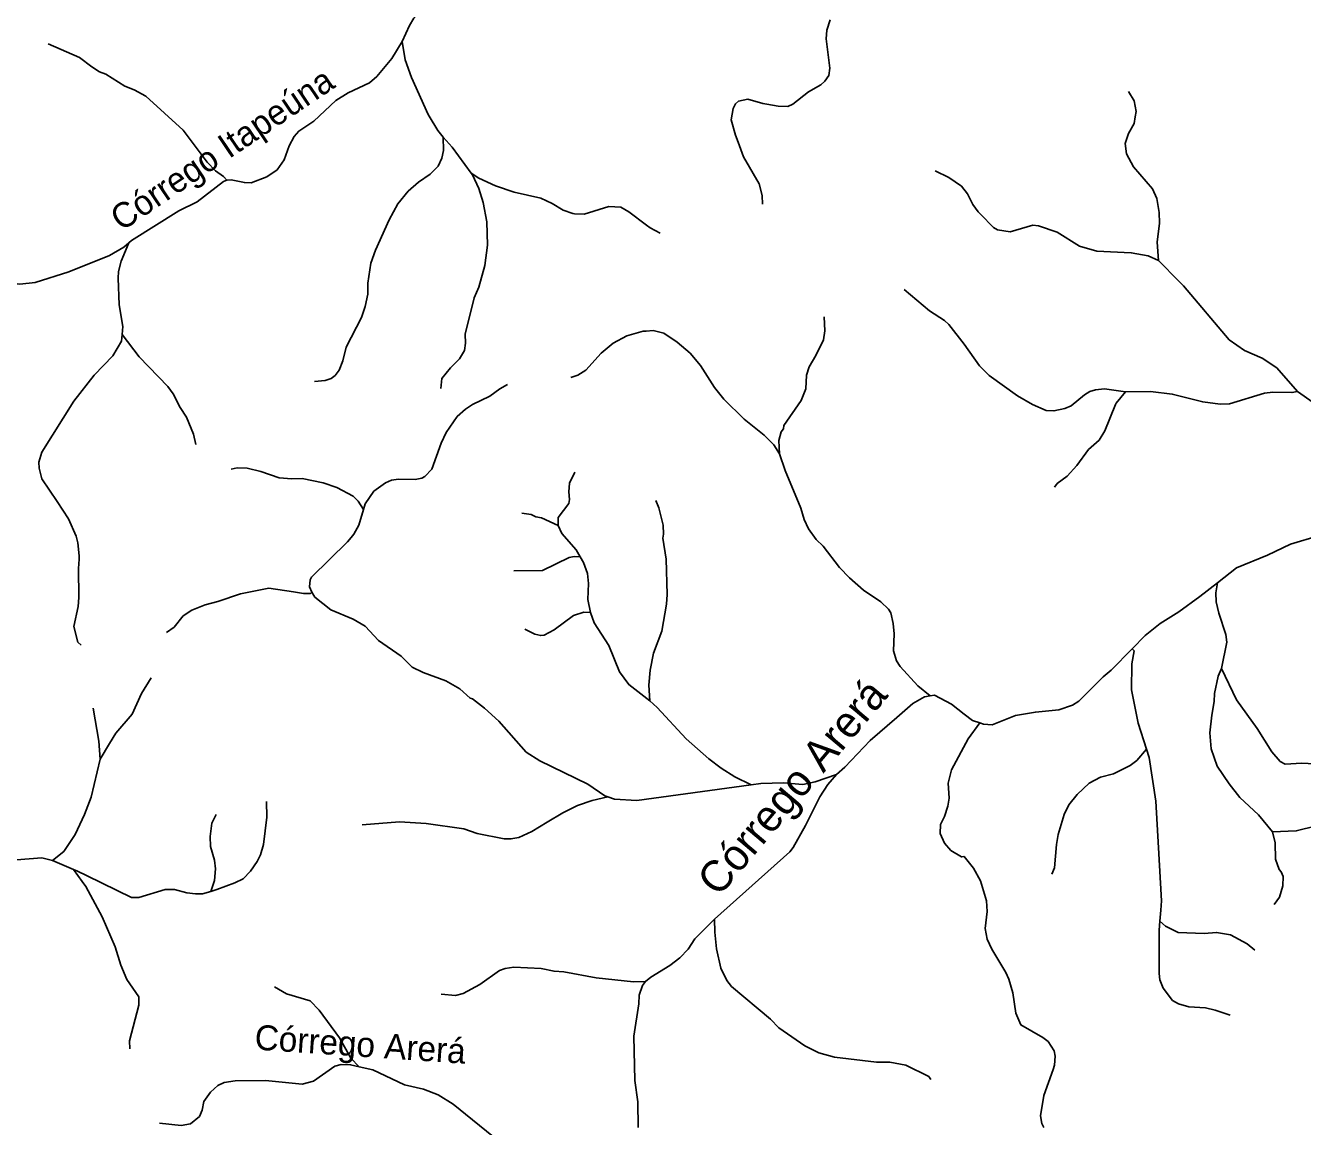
# Model space of a CAD drawing. Extents: x 317.8 to 344.1, y 7676.8 to 7704.8.
# Drawn here: x 321.463 to 325.558, y 7697.725 to 7701.254 of the extents above; entities that cross this region are included whole.
import ezdxf
from ezdxf.enums import TextEntityAlignment as Align

# ---------------------------------------------------------------- set-up
doc = ezdxf.new("R2010")
doc.units = 0
doc.header["$LTSCALE"] = 0.032
doc.layers.add('61', color=7, linetype='Continuous')
doc.layers.add('7', color=7, linetype='Continuous', lineweight=25)

msp = doc.modelspace()

# ---------------------------------------------------------------- linework, layer by layer
at = {"layer": '7'}
msp.add_line((321.6172, 7698.5491), (321.5497, 7698.5777), dxfattribs=at)
for points in [[(323.099, 7701.5157), (323.0656, 7701.5073), (322.979, 7701.4453), (322.9314, 7701.4175), (322.8796, 7701.394), (322.8477, 7701.3741), (322.7837, 7701.3208), (322.7513, 7701.3054), (322.7218, 7701.2914), (322.7088, 7701.2777), (322.6943, 7701.254), (322.6716, 7701.2027)], [(323.8262, 7700.6814), (323.8257, 7700.7098), (323.8156, 7700.7464), (323.7662, 7700.8337), (323.7485, 7700.88), (323.74, 7700.9024), (323.7264, 7700.9523), (323.7326, 7700.9881), (323.7404, 7701.003), (323.7502, 7701.0122), (323.7793, 7701.0181), (323.8282, 7701.0048), (323.8405, 7701.0025), (323.8773, 7700.9957), (323.9076, 7700.9949), (323.9242, 7701.0023), (323.9744, 7701.0413), (324.0135, 7701.0644), (324.0269, 7701.0759), (324.0393, 7701.0941), (324.0425, 7701.1179), (324.0312, 7701.212), (324.0329, 7701.2392), (324.0436, 7701.2721)], [(322.6716, 7701.2027), (322.638, 7701.1486), (322.5897, 7701.0903), (322.5661, 7701.0705), (322.4978, 7701.0384), (322.4584, 7701.0138), (322.3873, 7700.9478), (322.3396, 7700.9157), (322.3252, 7700.8982), (322.3088, 7700.8686), (322.2925, 7700.8232), (322.2707, 7700.7919), (322.237, 7700.7687), (322.1872, 7700.7502), (322.1653, 7700.751), (322.1226, 7700.7596), (322.1092, 7700.7589)], [(322.6716, 7701.2027), (322.6812, 7701.1443), (322.701, 7701.0875), (322.7549, 7700.9691), (322.7572, 7700.9641), (322.7854, 7700.9178), (322.8029, 7700.8968)], [(322.1092, 7700.7589), (322.0985, 7700.7706), (322.0729, 7700.7882), (322.0453, 7700.8159), (321.9688, 7700.9185), (321.8491, 7701.0279), (321.8119, 7701.0484), (321.7812, 7701.0601), (321.7206, 7701.0981), (321.7007, 7701.1062), (321.6761, 7701.1213), (321.6364, 7701.1521), (321.5357, 7701.196)], [(325.0963, 7700.5005), (325.0924, 7700.5597), (325.0996, 7700.6207), (325.0989, 7700.655), (325.0916, 7700.6993), (325.0772, 7700.7304), (325.0171, 7700.801), (324.9946, 7700.8428), (324.9897, 7700.8757), (325.0001, 7700.908), (325.0188, 7700.9406), (325.0224, 7700.9616), (325.0254, 7700.979), (325.019, 7701.0124), (325.0003, 7701.0428)], [(322.8029, 7700.8968), (322.8039, 7700.8531), (322.7981, 7700.8288), (322.7864, 7700.8037), (322.7609, 7700.7773), (322.7239, 7700.7517), (322.6908, 7700.7235), (322.6577, 7700.683), (322.6293, 7700.6312), (322.5858, 7700.5344), (322.5702, 7700.4922), (322.561, 7700.4282), (322.5609, 7700.3932), (322.5522, 7700.3531), (322.5405, 7700.3182), (322.4919, 7700.2231), (322.481, 7700.1796), (322.4695, 7700.1493), (322.4562, 7700.132), (322.443, 7700.1228), (322.4238, 7700.1162), (322.3898, 7700.1129)], [(322.8029, 7700.8968), (322.8315, 7700.8642), (322.8923, 7700.7812)], [(322.1092, 7700.7589), (322.0979, 7700.7538), (322.0135, 7700.6889), (321.955, 7700.6604), (321.8033, 7700.5653), (321.7949, 7700.5581)], [(322.8923, 7700.7812), (322.8964, 7700.7756), (322.9173, 7700.7316), (322.9309, 7700.6866), (322.9423, 7700.625), (322.9448, 7700.5506), (322.9358, 7700.4845), (322.9167, 7700.4159), (322.9022, 7700.3812), (322.8731, 7700.2645), (322.8746, 7700.236), (322.8707, 7700.2125), (322.8548, 7700.1859), (322.826, 7700.1571), (322.7982, 7700.1225), (322.7949, 7700.0909)], [(322.8923, 7700.7812), (322.9173, 7700.7652), (322.9704, 7700.7408), (323.0298, 7700.7199), (323.1162, 7700.7003), (323.1518, 7700.6841), (323.1872, 7700.6623), (323.2189, 7700.6519), (323.224, 7700.6502), (323.2546, 7700.6499), (323.3334, 7700.6744), (323.3727, 7700.6725), (323.3985, 7700.6568), (323.4544, 7700.6146), (323.4663, 7700.6056), (323.4982, 7700.5889)], [(325.0963, 7700.5005), (325.0638, 7700.5162), (325.0091, 7700.5259), (324.8987, 7700.5313), (324.8431, 7700.5474), (324.772, 7700.592), (324.7124, 7700.6123), (324.6941, 7700.614), (324.6212, 7700.5929), (324.5808, 7700.5989), (324.5672, 7700.607), (324.5257, 7700.6494), (324.5186, 7700.6566), (324.5013, 7700.6805), (324.4841, 7700.7146), (324.4646, 7700.7388), (324.4245, 7700.7666), (324.3801, 7700.7885)], [(321.7949, 7700.5581), (321.7781, 7700.5437), (321.7321, 7700.5167), (321.6019, 7700.465), (321.4946, 7700.4304), (321.4454, 7700.4256), (321.4203, 7700.4284)], [(321.7949, 7700.5581), (321.7696, 7700.4993), (321.7615, 7700.4657), (321.7598, 7700.4444), (321.7631, 7700.3589), (321.7755, 7700.2896), (321.7732, 7700.2639)], [(325.543, 7700.0809), (325.4765, 7700.1566), (325.4295, 7700.1874), (325.3725, 7700.2129), (325.3233, 7700.2469), (325.1769, 7700.4196), (325.1618, 7700.4348), (325.0963, 7700.5005)], [(324.2807, 7700.4079), (324.3624, 7700.3392), (324.4102, 7700.3092), (324.4244, 7700.2958), (324.4735, 7700.2332), (324.523, 7700.1631), (324.5539, 7700.1321), (324.6443, 7700.0675), (324.6929, 7700.039), (324.7366, 7700.0202), (324.7611, 7700.0189), (324.7959, 7700.0262), (324.8169, 7700.0352), (324.8595, 7700.0706), (324.8764, 7700.081), (324.8943, 7700.0867), (324.9236, 7700.0891), (324.9904, 7700.0798)], [(324.0249, 7700.3204), (324.0271, 7700.2751), (324.0222, 7700.2465), (323.9979, 7700.1962), (323.9763, 7700.1602), (323.9676, 7700.1337), (323.9652, 7700.0892), (323.9505, 7700.0526), (323.8952, 7699.9722), (323.8936, 7699.9609), (323.8868, 7699.9517), (323.8796, 7699.924), (323.8812, 7699.8813)], [(321.7732, 7700.2639), (321.7712, 7700.2419), (321.743, 7700.1953), (321.6832, 7700.1334), (321.6176, 7700.0498), (321.5156, 7699.8866), (321.5061, 7699.8542), (321.5071, 7699.8354), (321.5154, 7699.8012), (321.5644, 7699.7282), (321.6012, 7699.6734), (321.6261, 7699.617), (321.6309, 7699.5957), (321.6347, 7699.5543), (321.6357, 7699.5431), (321.6326, 7699.5141), (321.6342, 7699.421), (321.6316, 7699.3916), (321.6181, 7699.3273), (321.6311, 7699.2775), (321.6416, 7699.2677)], [(321.7732, 7700.2639), (321.8271, 7700.1921), (321.9198, 7700.0971), (321.9362, 7700.0731), (321.9588, 7700.0294), (321.9789, 7699.9987), (322.0016, 7699.9439), (322.0092, 7699.9116)], [(323.2124, 7700.1255), (323.234, 7700.133), (323.2602, 7700.1493), (323.3093, 7700.2036), (323.348, 7700.2365), (323.3921, 7700.2598), (323.4436, 7700.2741), (323.4534, 7700.2748), (323.4766, 7700.2766), (323.5104, 7700.2684), (323.5531, 7700.2397), (323.5946, 7700.2038), (323.6278, 7700.1639), (323.6724, 7700.0935), (323.7025, 7700.056), (323.7674, 7699.9928), (323.8318, 7699.9414), (323.8628, 7699.9104), (323.8812, 7699.8813)], [(323.0092, 7700.1039), (322.9842, 7700.0901), (322.9526, 7700.0662), (322.8962, 7700.0396), (322.8741, 7700.0249), (322.8472, 7700.0006), (322.812, 7699.9498), (322.7963, 7699.9153), (322.7663, 7699.8323), (322.744, 7699.8085), (322.7341, 7699.8031), (322.7129, 7699.7994), (322.6588, 7699.7998), (322.6365, 7699.7966), (322.6175, 7699.7886), (322.5804, 7699.7615), (322.552, 7699.7207), (322.547, 7699.7031)], [(324.9904, 7700.0798), (324.9609, 7700.0438), (324.9591, 7700.0394), (324.9247, 7699.9554), (324.9063, 7699.9251), (324.8719, 7699.895), (324.8345, 7699.8439), (324.8042, 7699.8102), (324.7718, 7699.7864), (324.7631, 7699.7747)], [(324.9904, 7700.0798), (325.0714, 7700.0811), (325.1408, 7700.0728), (325.2386, 7700.0476), (325.2946, 7700.0403), (325.3246, 7700.042), (325.4371, 7700.0761), (325.4637, 7700.0794), (325.5246, 7700.0778), (325.543, 7700.0809)], [(325.9044, 7699.9919), (325.8856, 7699.9809), (325.8465, 7699.9711), (325.7823, 7699.9735), (325.7146, 7699.9898), (325.6952, 7699.9945), (325.6409, 7700.0169), (325.5925, 7700.0453), (325.543, 7700.0809)], [(323.8812, 7699.8813), (323.8998, 7699.8279), (323.9494, 7699.7076), (323.9602, 7699.6711), (323.9746, 7699.6411), (323.9992, 7699.607), (324.0212, 7699.5849), (324.074, 7699.5173), (324.1053, 7699.4836), (324.1504, 7699.4443), (324.2067, 7699.4068), (324.2308, 7699.3834), (324.238, 7699.3715), (324.2463, 7699.3373), (324.2489, 7699.3042), (324.2467, 7699.25), (324.2562, 7699.218), (324.2681, 7699.1994), (324.3252, 7699.1374), (324.3645, 7699.1053)], [(325.9042, 7699.8821), (325.8881, 7699.8348), (325.8537, 7699.7659), (325.8062, 7699.6909), (325.778, 7699.6594), (325.7612, 7699.6497), (325.6927, 7699.6311), (325.6128, 7699.6197), (325.5201, 7699.5917), (325.4466, 7699.5568), (325.3465, 7699.5157), (325.2856, 7699.468)], [(322.547, 7699.7031), (322.5305, 7699.73), (322.5138, 7699.7456), (322.462, 7699.7738), (322.418, 7699.7885), (322.3502, 7699.8022), (322.3169, 7699.8007), (322.2768, 7699.8047), (322.2177, 7699.8247), (322.1742, 7699.8348), (322.142, 7699.8366), (322.1225, 7699.8325)], [(323.2253, 7699.8229), (323.2073, 7699.7868), (323.2056, 7699.7596), (323.2081, 7699.7348), (323.2057, 7699.7223), (323.1715, 7699.6767), (323.1718, 7699.651)], [(323.4842, 7699.7316), (323.4941, 7699.7081), (323.5079, 7699.6531), (323.5096, 7699.6234), (323.5073, 7699.6109), (323.5177, 7699.5439), (323.5209, 7699.4308), (323.5185, 7699.3989), (323.5038, 7699.3125), (323.4776, 7699.2418), (323.4663, 7699.1883), (323.4623, 7699.1401), (323.4651, 7699.09)], [(322.547, 7699.7031), (322.5326, 7699.6522), (322.5162, 7699.6241), (322.5071, 7699.6126), (322.4963, 7699.5991), (322.3802, 7699.4863), (322.376, 7699.4776), (322.3742, 7699.4549), (322.3817, 7699.4373)], [(323.1718, 7699.651), (323.1179, 7699.6758), (323.0999, 7699.6792), (323.0847, 7699.6865), (323.0549, 7699.6915)], [(323.1718, 7699.651), (323.1829, 7699.6264), (323.229, 7699.5736), (323.2423, 7699.551)], [(323.2423, 7699.551), (323.2232, 7699.552), (323.2064, 7699.5488), (323.1211, 7699.5073), (323.0288, 7699.5065)], [(323.2423, 7699.551), (323.2529, 7699.533), (323.2659, 7699.4976), (323.2684, 7699.4656), (323.2668, 7699.4145), (323.2753, 7699.3722)], [(321.9151, 7699.3088), (321.9395, 7699.3261), (321.9686, 7699.3617), (321.9961, 7699.3801), (322.0398, 7699.3971), (322.0803, 7699.4074), (322.153, 7699.4323), (322.2439, 7699.4502), (322.3229, 7699.4386), (322.3544, 7699.434), (322.3769, 7699.434), (322.3817, 7699.4373)], [(325.2856, 7699.468), (325.2294, 7699.424), (325.162, 7699.3752), (325.1023, 7699.3373), (325.054, 7699.2986), (325.0128, 7699.2567)], [(325.2987, 7699.1927), (325.3164, 7699.2776), (325.3125, 7699.3021), (325.2901, 7699.3707), (325.2821, 7699.4066), (325.2807, 7699.4358), (325.2856, 7699.468)], [(322.3817, 7699.4373), (322.3913, 7699.4222), (322.4419, 7699.381), (322.5141, 7699.3509), (322.5519, 7699.3287), (322.5954, 7699.2829), (322.668, 7699.2332), (322.703, 7699.1969), (322.7382, 7699.1803), (322.8108, 7699.1537), (322.8557, 7699.1278), (322.8891, 7699.0984), (322.8966, 7699.0957), (322.9353, 7699.0661), (322.9812, 7699.0242), (323.0693, 7698.9248), (323.1124, 7698.897), (323.267, 7698.822), (323.3208, 7698.7849), (323.3304, 7698.7815)], [(323.0647, 7699.3191), (323.097, 7699.3034), (323.1156, 7699.2987), (323.1266, 7699.2996), (323.1583, 7699.3174), (323.2206, 7699.3627), (323.2539, 7699.3734), (323.2753, 7699.3722)], [(323.2753, 7699.3722), (323.2872, 7699.3395), (323.3343, 7699.2668), (323.3682, 7699.1828), (323.3979, 7699.1414), (323.4651, 7699.09)], [(325.0128, 7699.2567), (324.9447, 7699.1876), (324.919, 7699.1669), (324.8411, 7699.088), (324.8206, 7699.0752), (324.7773, 7699.0604), (324.7019, 7699.0533), (324.6379, 7699.0421), (324.5629, 7699.0127), (324.5355, 7699.0152), (324.5236, 7699.0189)], [(325.0128, 7699.2567), (325.0182, 7699.2503), (325.0117, 7699.2077), (325.0101, 7699.1247), (325.0312, 7699.0174), (325.0585, 7698.9341)], [(321.7021, 7698.9025), (321.733, 7698.9525), (321.7533, 7698.9854), (321.8055, 7699.0471), (321.8353, 7699.1131), (321.8666, 7699.1634)], [(325.4619, 7698.6698), (325.417, 7698.7238), (325.358, 7698.7797), (325.3229, 7698.8235), (325.2848, 7698.8801), (325.2847, 7698.8804), (325.266, 7698.9356), (325.2619, 7698.9868), (325.2676, 7699.0438), (325.2756, 7699.0876), (325.2765, 7699.1133), (325.2882, 7699.1685), (325.2987, 7699.1927)], [(325.2987, 7699.1927), (325.3467, 7699.0931), (325.4128, 7699.0008), (325.4605, 7698.9256), (325.4866, 7698.8954), (325.5027, 7698.8864), (325.5563, 7698.8895), (325.5974, 7698.8877), (325.6424, 7698.8699), (325.6816, 7698.848), (325.7193, 7698.852), (325.7428, 7698.8503), (325.7562, 7698.8416), (325.7884, 7698.7999)], [(323.4651, 7699.09), (323.4894, 7699.0685), (323.5824, 7698.9675), (323.6548, 7698.9033), (323.6942, 7698.8732), (323.7378, 7698.8455), (323.7902, 7698.82)], [(324.3645, 7699.1053), (324.3463, 7699.1021), (324.3088, 7699.0811), (324.2573, 7699.0365), (324.1716, 7698.9623), (324.0905, 7698.877), (324.0638, 7698.8535)], [(324.5236, 7699.0189), (324.4999, 7699.0264), (324.4736, 7699.0469), (324.433, 7699.0785), (324.3787, 7699.1078), (324.3645, 7699.1053)], [(321.7021, 7698.9025), (321.6978, 7698.9604), (321.68, 7699.0656)], [(324.5236, 7699.0189), (324.4858, 7698.968), (324.4334, 7698.868), (324.4224, 7698.8259), (324.4249, 7698.7779), (324.4208, 7698.7521), (324.4104, 7698.7183), (324.3972, 7698.6929), (324.3964, 7698.6638), (324.4109, 7698.633), (324.4312, 7698.6093), (324.4651, 7698.5889), (324.473, 7698.5908), (324.5029, 7698.5535), (324.5258, 7698.5124), (324.5455, 7698.4479), (324.547, 7698.4147), (324.5406, 7698.3593), (324.5473, 7698.3256), (324.5619, 7698.2934), (324.6068, 7698.2183), (324.6166, 7698.1968), (324.6294, 7698.1539), (324.6395, 7698.0887), (324.6553, 7698.0504), (324.7261, 7698.0102), (324.7426, 7697.9978), (324.7623, 7697.9675), (324.7656, 7697.9502), (324.7631, 7697.9211), (324.7585, 7697.9081), (324.7288, 7697.824), (324.7183, 7697.7587), (324.7221, 7697.7344), (324.7288, 7697.7219)], [(325.0585, 7698.9341), (325.0269, 7698.8982), (325.0054, 7698.8823), (324.9519, 7698.8552), (324.9111, 7698.8453), (324.8739, 7698.8251), (324.8354, 7698.7889), (324.8093, 7698.7564), (324.7938, 7698.7253), (324.7751, 7698.6611), (324.7696, 7698.6286), (324.7629, 7698.5542), (324.7542, 7698.5342)], [(325.0585, 7698.9341), (325.0671, 7698.9079), (325.0883, 7698.7677), (325.0967, 7698.6179), (325.1062, 7698.4484), (325.1039, 7698.4185), (325.1011, 7698.3829)], [(321.5497, 7698.5777), (321.5861, 7698.6068), (321.6227, 7698.6605), (321.6527, 7698.7246), (321.6737, 7698.7806), (321.7021, 7698.9025)], [(324.0638, 7698.8535), (324.0358, 7698.8216), (324.011, 7698.7814), (323.9651, 7698.6898), (323.9251, 7698.6191), (323.9144, 7698.6056), (323.6728, 7698.3898)], [(323.7902, 7698.82), (323.8217, 7698.8242), (323.8939, 7698.8268), (323.9566, 7698.8214), (323.9958, 7698.8298), (324.0638, 7698.8535)], [(323.3304, 7698.7815), (323.352, 7698.7738), (323.4235, 7698.7705), (323.7902, 7698.82)], [(322.2362, 7698.7668), (322.2366, 7698.7163), (322.2266, 7698.6288), (322.2172, 7698.5961), (322.2062, 7698.5741), (322.1848, 7698.5437), (322.1613, 7698.5193), (322.1341, 7698.5058), (322.0772, 7698.4843), (322.0579, 7698.4788)], [(323.3304, 7698.7815), (323.2806, 7698.7696), (323.2339, 7698.7544), (323.1866, 7698.73), (323.1366, 7698.7001), (323.0872, 7698.6705), (323.0451, 7698.6518), (323.02, 7698.6468), (322.9983, 7698.6467), (322.9119, 7698.6647), (322.8689, 7698.6794), (322.7482, 7698.6963), (322.663, 7698.7021), (322.5431, 7698.6915)], [(322.0746, 7698.7255), (322.0604, 7698.6976), (322.0556, 7698.655), (322.0569, 7698.6228), (322.0688, 7698.5784), (322.0728, 7698.5505), (322.0693, 7698.5131), (322.0579, 7698.4788)], [(325.4619, 7698.6698), (325.5384, 7698.6727), (325.603, 7698.6889), (325.6232, 7698.6904), (325.6365, 7698.6795), (325.6449, 7698.667), (325.6547, 7698.5831)], [(325.4675, 7698.4361), (325.4843, 7698.4603), (325.495, 7698.4962), (325.4961, 7698.5263), (325.49, 7698.5414), (325.4836, 7698.5484), (325.4722, 7698.5819), (325.4705, 7698.6348), (325.4619, 7698.6698)], [(321.5497, 7698.5777), (321.5155, 7698.5861), (321.3933, 7698.5766), (321.3529, 7698.5813), (321.3024, 7698.5782), (321.2613, 7698.5684), (321.2424, 7698.5592), (321.1273, 7698.5309), (321.0448, 7698.5395), (321.0199, 7698.5391), (320.9999, 7698.5311), (320.9869, 7698.5209), (320.9515, 7698.4773), (320.9312, 7698.4654)], [(322.0579, 7698.4788), (322.0312, 7698.4713), (322.0084, 7698.4705), (321.9802, 7698.4744), (321.9407, 7698.4852), (321.911, 7698.4852), (321.827, 7698.4592), (321.8033, 7698.4592), (321.6609, 7698.5285), (321.6275, 7698.5448), (321.6172, 7698.5491)], [(321.6172, 7698.5491), (321.6451, 7698.5099), (321.6564, 7698.4939), (321.7086, 7698.3976), (321.7502, 7698.3012), (321.7689, 7698.2421), (321.7881, 7698.1962), (321.8265, 7698.141), (321.8265, 7698.1144), (321.7961, 7697.9991), (321.7973, 7697.9735)], [(323.6728, 7698.3898), (323.6097, 7698.3261), (323.5882, 7698.2931), (323.5612, 7698.2654), (323.5293, 7698.2407), (323.4683, 7698.2039), (323.4513, 7698.1901)], [(323.6728, 7698.3898), (323.6735, 7698.3481), (323.679, 7698.2944), (323.6928, 7698.2324), (323.7127, 7698.1932), (323.7268, 7698.1743), (323.8522, 7698.0686), (323.8791, 7698.0415), (323.9622, 7697.9839), (324.0073, 7697.9613), (324.0578, 7697.9469), (324.1924, 7697.9311), (324.2348, 7697.931), (324.2869, 7697.9211), (324.3601, 7697.8854), (324.3671, 7697.8757)], [(325.1011, 7698.3829), (325.0989, 7698.3547), (325.0989, 7698.2151), (325.1014, 7698.1951), (325.1113, 7698.1681), (325.1418, 7698.1285), (325.1614, 7698.1178), (325.1939, 7698.1087), (325.247, 7698.1053), (325.2784, 7698.0983), (325.3271, 7698.0819)], [(325.4061, 7698.2907), (325.3813, 7698.311), (325.3279, 7698.3393), (325.2829, 7698.3474), (325.2434, 7698.3435), (325.1602, 7698.3473), (325.1187, 7698.3677), (325.1011, 7698.3829)], [(323.4513, 7698.1901), (323.4132, 7698.1886), (323.2933, 7698.2017), (323.1893, 7698.2211), (323.1583, 7698.2228), (323.1166, 7698.2317), (323.0295, 7698.2358), (323.0016, 7698.2313), (322.9837, 7698.225), (322.9197, 7698.1797), (322.8664, 7698.1511), (322.8424, 7698.1446), (322.7957, 7698.1487)], [(322.2616, 7698.1724), (322.3003, 7698.1498), (322.3765, 7698.1281), (322.4047, 7698.0978), (322.4696, 7698.0092), (322.5068, 7697.9445), (322.5336, 7697.9166)], [(323.4513, 7698.1901), (323.4421, 7698.1766), (323.431, 7698.1455), (323.4306, 7698.118), (323.4142, 7698.0144), (323.4175, 7697.8729), (323.4272, 7697.8038), (323.428, 7697.7222)], [(322.5336, 7697.9166), (322.5054, 7697.9228), (322.4753, 7697.9236), (322.4552, 7697.9185), (322.3868, 7697.8706), (322.3501, 7697.861), (322.2323, 7697.8724), (322.1356, 7697.8715), (322.1003, 7697.8655), (322.0796, 7697.8568), (322.0567, 7697.8351), (322.0352, 7697.8051), (322.0295, 7697.7774)], [(323.0254, 7697.655), (322.9806, 7697.6776), (322.835, 7697.7963), (322.7864, 7697.8269), (322.7395, 7697.8443), (322.6784, 7697.859), (322.5771, 7697.9071), (322.5336, 7697.9166)], [(322.0295, 7697.7774), (322.0209, 7697.7572), (321.9922, 7697.7336), (321.9622, 7697.7281), (321.8927, 7697.7355)]]:
    msp.add_lwpolyline(points, dxfattribs=at)

# ---------------------------------------------------------------- texts
at = {"layer": '61'}
for s, height, rotation, p in [('Córrego Itapeúna', 0.08, 33.996, (322.1158, 7700.8256)), ('Córrego Arerá', 0.1, 49.844, (323.9595, 7698.7818)), ('Córrego Arerá', 0.08, 356.114, (322.5342, 7697.949))]:
    msp.add_text(s, height=height, rotation=rotation, dxfattribs=at).set_placement(p, align=Align.CENTER)

doc.saveas('drawing.dxf')
